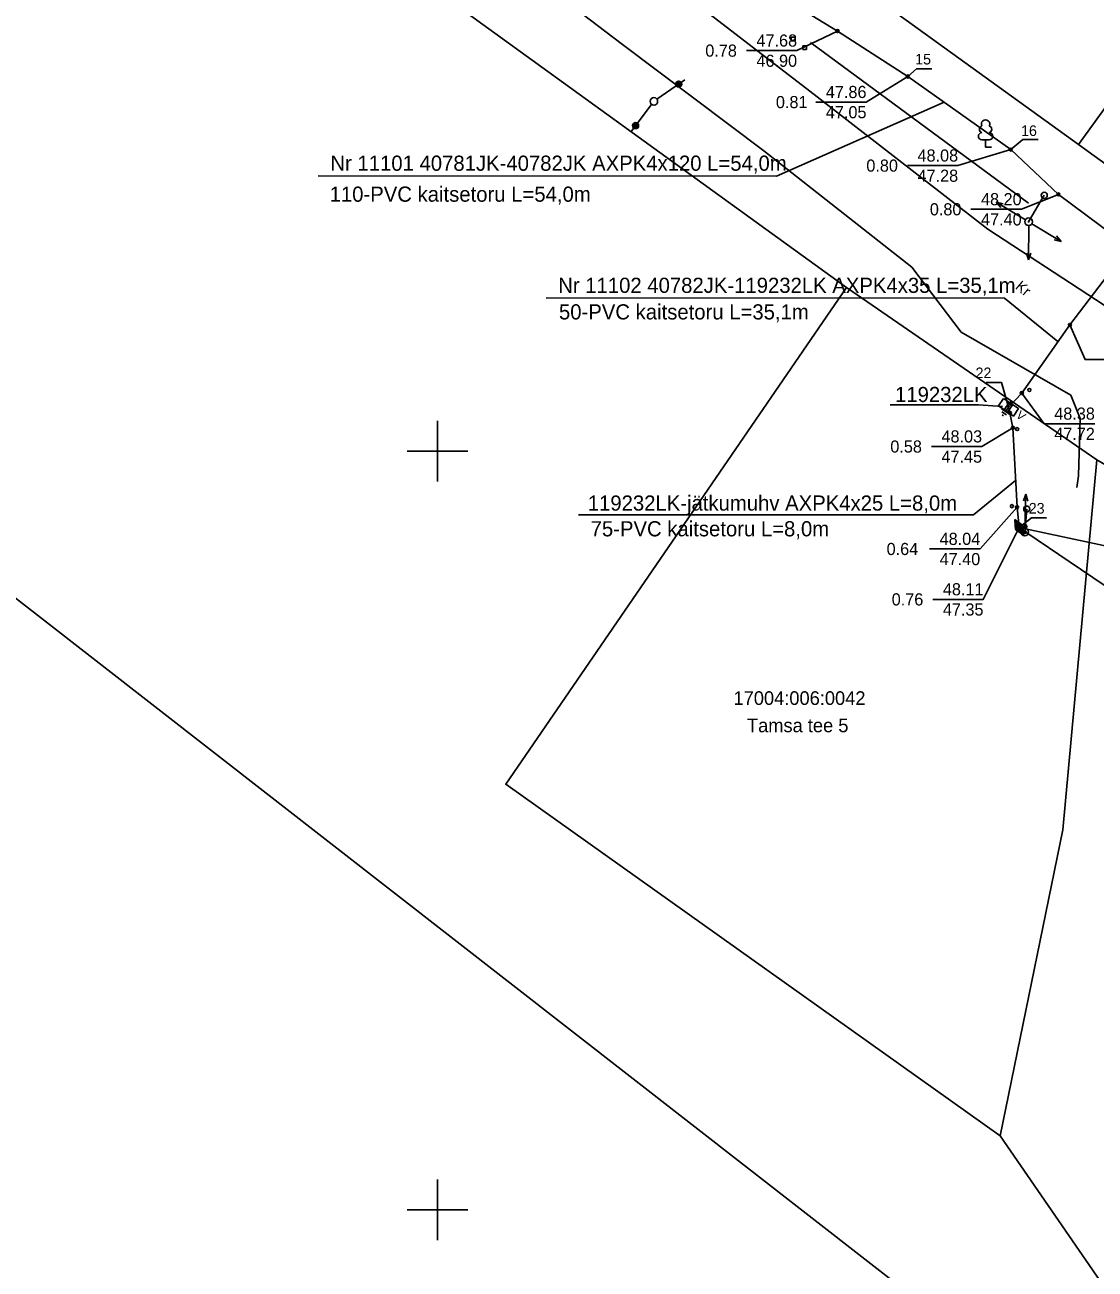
# Model space of a CAD drawing. Extents: x 643977 to 644381, y 6457457 to 6457867.
# Drawn here: x 644122.8 to 644193.3, y 6457546.1 to 6457628.1 of the extents above; entities that cross this region are included whole.
import ezdxf

# ---------------------------------------------------------------- set-up
doc = ezdxf.new("R2010")
doc.units = 0
for name, color, linetype in [('004 MPP EE @ 1 (1)', 7, 'Continuous'), ('005 MPO EE @ 1 (1)', 7, 'Continuous'), ('005 MPO EE @ 1 (2)', 7, 'Continuous'), ('007 PIIR EE', 7, 'Continuous'), ('007 PIIR1 EE', 7, 'Continuous'), ('MOOTMPUNKT', 7, 'Continuous'), ('TEE', 7, 'Continuous'), ('TORU_NR', 7, 'Continuous'), ('UUS', 7, 'Continuous'), ('Veeprojekti jooned$0$0_Hoiatustekst', 7, 'Continuous'), ('VORK', 7, 'Continuous'), ('VORMISTUS', 7, 'Continuous')]:
    doc.layers.add(name, color=color, linetype=linetype)

msp = doc.modelspace()

# ---------------------------------------------------------------- linework, layer by layer
at = {"layer": '004 MPP EE @ 1 (1)'}
for p, q in [((644173.309, 6457627.298), (644173.309, 6457627.048)), ((644173.309, 6457627.298), (644173.559, 6457627.298)), ((644173.559, 6457627.298), (644173.559, 6457627.048)), ((644173.309, 6457627.048), (644173.559, 6457627.048)), ((644174.072, 6457626.717), (644174.072, 6457626.467)), ((644174.072, 6457626.717), (644174.322, 6457626.717)), ((644174.072, 6457626.467), (644174.322, 6457626.467)), ((644174.322, 6457626.717), (644174.322, 6457626.467))]:
    msp.add_line(p, q, dxfattribs=at)
at = {"layer": '005 MPO EE @ 1 (1)'}
for p, q in [((644189.982, 6457616.865), (644188.956, 6457615.125)), ((644187.678, 6457603.219), (644187.342, 6457602.726)), ((644187.902, 6457603.067), (644187.566, 6457602.573)), ((644188.697, 6457594.667), (644188.83, 6457596.183))]:
    msp.add_line(p, q, dxfattribs=at)
msp.add_lwpolyline([(644187.296, 6457603.479), (644188.284, 6457602.807), (644187.948, 6457602.313), (644186.96, 6457602.986)], close=True, dxfattribs=at)
msp.add_lwpolyline([(644179.824, 6457603.066), (644185.644, 6457603.066), (644187.227, 6457602.95)], dxfattribs=at)
for centre, radius in [((644164.252, 6457623.055), 0.25), ((644189.982, 6457616.865), 0.2), ((644188.956, 6457615.125), 0.25), ((644188.956, 6457615.125), 0.0234), ((644188.83, 6457596.183), 0.2), ((644188.697, 6457594.667), 0.25), ((644188.697, 6457594.667), 0.0234)]:
    msp.add_circle(centre, radius, dxfattribs=at)
at = {"layer": '005 MPO EE @ 1 (2)'}
for points in [[(644097.357, 6457696.766), (644100.441, 6457690.483), (644108.831, 6457675.729), (644120.122, 6457661.417), (644132.967, 6457649.318), (644147.713, 6457637.831), (644162.185, 6457626.8)], [(644165.209, 6457630.911), (644174.337, 6457623.878), (644186.272, 6457614.624), (644201.035, 6457604.979), (644215.289, 6457597.386), (644225.394, 6457591.42), (644240.377, 6457581.381), (644253.475, 6457570.785), (644267.864, 6457559.308)], [(644162.185, 6457626.8), (644171.491, 6457619.794), (644181.248, 6457612.122), (644184.497, 6457607.838)], [(644184.497, 6457607.838), (644191.733, 6457603.701), (644192.353, 6457602.158), (644192.243, 6457598.378), (644192.129, 6457597.598)]]:
    msp.add_lwpolyline(points, dxfattribs=at)
at = {"layer": '007 PIIR EE'}
for p, q in [((644186.818, 6457616.421), (644187.126, 6457616.059)), ((644186.818, 6457616.421), (644187.281, 6457616.314)), ((644188.742, 6457615.254), (644186.818, 6457616.421)), ((644188.958, 6457614.861), (644188.954, 6457612.611)), ((644189.169, 6457614.995), (644191.093, 6457613.828)), ((644191.093, 6457613.828), (644190.785, 6457614.191)), ((644191.093, 6457613.828), (644190.63, 6457613.936)), ((644188.954, 6457612.611), (644188.806, 6457613.062)), ((644188.954, 6457612.611), (644189.105, 6457613.061)), ((644188.767, 6457597.166), (644188.605, 6457596.719)), ((644188.704, 6457594.917), (644188.767, 6457597.166)), ((644188.767, 6457597.166), (644188.903, 6457596.71)), ((644188.697, 6457594.667), (644188.697, 6457594.667))]:
    msp.add_line(p, q, dxfattribs=at)
at = {"layer": '007 PIIR1 EE'}
for p, q in [((644188.037, 6457595.497), (644188.561, 6457595.107)), ((644188.037, 6457595.497), (644188.086, 6457594.845)), ((644188.06, 6457595.479), (644188.04, 6457595.45)), ((644188.08, 6457595.464), (644188.043, 6457595.409)), ((644188.1, 6457595.449), (644188.046, 6457595.369)), ((644188.12, 6457595.434), (644188.049, 6457595.328)), ((644188.141, 6457595.42), (644188.052, 6457595.288)), ((644188.161, 6457595.405), (644188.056, 6457595.248)), ((644188.181, 6457595.39), (644188.059, 6457595.207)), ((644188.201, 6457595.375), (644188.062, 6457595.167)), ((644188.221, 6457595.36), (644188.065, 6457595.126)), ((644188.241, 6457595.345), (644188.068, 6457595.086)), ((644188.261, 6457595.33), (644188.071, 6457595.046)), ((644188.281, 6457595.315), (644188.074, 6457595.005)), ((644188.301, 6457595.3), (644188.077, 6457594.965)), ((644188.321, 6457595.285), (644188.08, 6457594.924)), ((644188.341, 6457595.27), (644188.083, 6457594.884)), ((644188.361, 6457595.255), (644188.087, 6457594.845)), ((644188.382, 6457595.24), (644188.107, 6457594.83)), ((644188.402, 6457595.225), (644188.127, 6457594.815)), ((644188.422, 6457595.21), (644188.147, 6457594.8)), ((644188.442, 6457595.195), (644188.167, 6457594.785)), ((644188.462, 6457595.181), (644188.187, 6457594.77)), ((644188.482, 6457595.166), (644188.207, 6457594.755)), ((644188.502, 6457595.151), (644188.227, 6457594.74)), ((644188.522, 6457595.136), (644188.247, 6457594.725)), ((644188.61, 6457594.455), (644188.086, 6457594.845)), ((644188.542, 6457595.121), (644188.267, 6457594.71)), ((644188.561, 6457595.104), (644188.287, 6457594.695)), ((644188.564, 6457595.064), (644188.307, 6457594.68)), ((644188.567, 6457595.023), (644188.328, 6457594.665)), ((644188.57, 6457594.983), (644188.348, 6457594.65)), ((644188.573, 6457594.942), (644188.368, 6457594.635)), ((644188.576, 6457594.902), (644188.388, 6457594.621)), ((644188.579, 6457594.862), (644188.408, 6457594.606)), ((644188.582, 6457594.821), (644188.428, 6457594.591)), ((644188.585, 6457594.781), (644188.448, 6457594.576)), ((644188.588, 6457594.74), (644188.468, 6457594.561)), ((644188.591, 6457594.7), (644188.488, 6457594.546)), ((644188.594, 6457594.66), (644188.508, 6457594.531)), ((644188.597, 6457594.619), (644188.528, 6457594.516)), ((644188.601, 6457594.579), (644188.548, 6457594.501)), ((644188.61, 6457594.455), (644188.561, 6457595.107)), ((644188.604, 6457594.538), (644188.569, 6457594.486)), ((644188.607, 6457594.498), (644188.589, 6457594.471)), ((644188.61, 6457594.457), (644188.609, 6457594.456))]:
    msp.add_line(p, q, dxfattribs=at)
for points in [[(644170.747, 6457632.71), (644170.727, 6457632.25), (644170.665, 6457631.798), (644170.489, 6457631.288), (644176.355, 6457627.696), (644180.988, 6457624.699), (644187.779, 6457619.88), (644190.918, 6457616.922), (644195.569, 6457613.471), (644203.702, 6457608.165), (644207.658, 6457605.551), (644212.132, 6457602.911), (644212.432, 6457603.018), (644212.719, 6457603.524), (644212.727, 6457604.721)], [(644170.747, 6457632.71), (644170.727, 6457632.25), (644170.665, 6457631.798), (644170.489, 6457631.288), (644176.355, 6457627.696), (644180.988, 6457624.699), (644187.779, 6457619.88), (644190.918, 6457616.922), (644195.569, 6457613.471), (644203.702, 6457608.165), (644207.658, 6457605.551), (644212.132, 6457602.911), (644212.432, 6457603.018), (644212.719, 6457603.524), (644212.727, 6457604.721)], [(644176.355, 6457627.696), (644173.682, 6457626.404), (644170.348, 6457626.404)], [(644180.988, 6457624.699), (644178.256, 6457623.012), (644174.922, 6457623.012)], [(644142.134, 6457618.16), (644172.343, 6457618.134), (644183.391, 6457622.999)], [(644187.779, 6457619.88), (644184.297, 6457618.825), (644180.964, 6457618.825)], [(644190.918, 6457616.922), (644188.482, 6457615.945), (644185.148, 6457615.945)], [(644187.622, 6457602.896), (644188.506, 6457603.833), (644191.675, 6457608.319), (644195.483, 6457613.348), (644203.62, 6457608.04), (644207.578, 6457605.424), (644211.895, 6457602.8), (644212.158, 6457602.721), (644212.49, 6457602.886), (644212.75, 6457603.471), (644212.727, 6457604.721)], [(644187.622, 6457602.896), (644188.506, 6457603.833), (644191.675, 6457608.319), (644195.483, 6457613.348), (644203.62, 6457608.04), (644207.578, 6457605.424), (644211.895, 6457602.8), (644212.158, 6457602.721), (644212.49, 6457602.886), (644212.75, 6457603.471), (644212.727, 6457604.721)], [(644157.147, 6457610.11), (644187.357, 6457610.084), (644190.883, 6457607.238)], [(644191.675, 6457608.319), (644192.671, 6457606.04), (644196.005, 6457606.04)], [(644188.506, 6457603.833), (644189.976, 6457601.811), (644193.309, 6457601.811)], [(644187.692, 6457602.437), (644187.168, 6457602.797)], [(644187.496, 6457602.389), (644187.193, 6457602.598)], [(644187.622, 6457602.896), (644187.43, 6457602.617)], [(644187.622, 6457602.896), (644187.715, 6457602.53), (644187.919, 6457601.541), (644188.19, 6457596.306), (644188.326, 6457594.977)], [(644187.622, 6457602.896), (644187.715, 6457602.53), (644187.919, 6457601.541), (644188.19, 6457596.306), (644188.326, 6457594.977)], [(644187.301, 6457602.341), (644187.219, 6457602.398)], [(644187.919, 6457601.541), (644185.877, 6457600.308), (644182.544, 6457600.308)], [(644188.099, 6457598.062), (644185.31, 6457595.795), (644159.293, 6457595.795)], [(644188.19, 6457596.306), (644185.754, 6457593.554), (644182.42, 6457593.554)], [(644188.326, 6457594.977), (644185.968, 6457590.232), (644182.635, 6457590.232)], [(644188.326, 6457594.977), (644188.697, 6457594.667), (644188.76, 6457594.652), (644199.031, 6457587.724)], [(644188.326, 6457594.977), (644194.624, 6457593.629), (644201.578, 6457593.629)]]:
    msp.add_lwpolyline(points, dxfattribs=at)
at = {"layer": 'MOOTMPUNKT'}
for centre in [(644176.355, 6457627.696), (644180.988, 6457624.699), (644187.779, 6457619.88), (644190.918, 6457616.922), (644191.675, 6457608.319), (644188.506, 6457603.833), (644189.002, 6457604.037), (644187.715, 6457602.53), (644187.79, 6457603.143), (644187.919, 6457601.541), (644188.199, 6457601.457), (644187.852, 6457596.376), (644188.19, 6457596.306), (644188.745, 6457595.044), (644188.326, 6457594.977), (644188.697, 6457594.667)]:
    msp.add_circle(centre, 0.1, dxfattribs=at)
at = {"layer": 'TEE'}
msp.add_lwpolyline([(644119.21, 6457655.5), (644137.18, 6457639.57), (644176.94, 6457610.8), (644193.44, 6457599.42), (644220.94, 6457583.42), (644258.83, 6457557.54), (644299.64, 6457526.51), (644330.13, 6457505.12), (644351.66, 6457500.83), (644373.13, 6457501.25), (644368.81, 6457508.24), (644366.6, 6457513.63), (644352.78, 6457513.35), (644335.16, 6457516.88), (644304.29, 6457538.7), (644233.94, 6457592.97), (644213.34, 6457605.08), (644212.32, 6457605.7), (644192.23, 6457620.22), (644172.44, 6457634.51), (644128.57, 6457664.58), (644105.62, 6457695.4)], dxfattribs=at)
for points in [[(644226.91, 6457668.24), (644207.22, 6457681.69), (644202.24, 6457674.99), (644172.44, 6457634.51), (644192.23, 6457620.22), (644221.58, 6457660.75)], [(644239.59, 6457656.82), (644226.91, 6457668.24), (644221.58, 6457660.75), (644192.23, 6457620.22), (644212.32, 6457605.7), (644228.29, 6457625.32), (644245.1, 6457645.66)], [(644176.94, 6457610.8), (644154.49, 6457578.04), (644187.08, 6457554.88), (644191.21, 6457575.04), (644193.44, 6457599.42)], [(644187.08, 6457554.88), (644204.95, 6457528.94), (644258.83, 6457557.54), (644220.94, 6457583.42), (644193.44, 6457599.42), (644191.21, 6457575.04)]]:
    msp.add_lwpolyline(points, close=True, dxfattribs=at)
at = {"layer": 'TORU_NR'}
msp.add_line((644174.581, 6457626.935), (644188.94, 6457616.351), dxfattribs=at)
at = {"layer": 'UUS'}
for points in [[(644180.988, 6457624.699), (644181.573, 6457625.199), (644182.573, 6457625.199)], [(644187.779, 6457619.88), (644188.572, 6457620.543), (644189.572, 6457620.543)], [(644187.622, 6457602.896), (644187.164, 6457604.521), (644186.164, 6457604.521)], [(644188.326, 6457594.977), (644189.137, 6457595.613), (644190.137, 6457595.613)]]:
    msp.add_lwpolyline(points, dxfattribs=at)
at = {"layer": 'Veeprojekti jooned$0$0_Hoiatustekst'}
for p, q in [((644164.457, 6457623.197), (644166.296, 6457624.478)), ((644164.101, 6457622.855), (644162.753, 6457621.065))]:
    msp.add_line(p, q, dxfattribs=at)
for centre, radius in [((644165.889, 6457624.194), 0.199), ((644165.889, 6457624.194), 0.19), ((644165.889, 6457624.194), 0.18), ((644165.889, 6457624.194), 0.171), ((644165.889, 6457624.194), 0.162), ((644165.889, 6457624.194), 0.152), ((644165.889, 6457624.194), 0.143), ((644165.889, 6457624.194), 0.133), ((644165.889, 6457624.194), 0.124), ((644165.889, 6457624.194), 0.114), ((644165.889, 6457624.194), 0.105), ((644165.889, 6457624.194), 0.0953), ((644165.889, 6457624.194), 0.0858), ((644165.889, 6457624.194), 0.0763), ((644165.889, 6457624.194), 0.0669), ((644165.889, 6457624.194), 0.0574), ((644165.889, 6457624.194), 0.0479), ((644165.889, 6457624.194), 0.0385), ((644165.889, 6457624.194), 0.029), ((644165.889, 6457624.194), 0.0195), ((644165.889, 6457624.194), 0.0101), ((644165.889, 6457624.194), 0.00061), ((644163.051, 6457621.461), 0.199), ((644163.051, 6457621.461), 0.19), ((644163.051, 6457621.461), 0.18), ((644163.051, 6457621.461), 0.171), ((644163.051, 6457621.461), 0.162), ((644163.051, 6457621.461), 0.152), ((644163.051, 6457621.461), 0.143), ((644163.051, 6457621.461), 0.133), ((644163.051, 6457621.461), 0.124), ((644163.051, 6457621.461), 0.114), ((644163.051, 6457621.461), 0.105), ((644163.051, 6457621.461), 0.0953), ((644163.051, 6457621.461), 0.0858), ((644163.051, 6457621.461), 0.0763), ((644163.051, 6457621.461), 0.0669), ((644163.051, 6457621.461), 0.0574), ((644163.051, 6457621.461), 0.0479), ((644163.051, 6457621.461), 0.0385), ((644163.051, 6457621.461), 0.029), ((644163.051, 6457621.461), 0.0195), ((644163.051, 6457621.461), 0.0101), ((644163.051, 6457621.461), 0.00061)]:
    msp.add_circle(centre, radius, dxfattribs=at)
at = {"layer": 'VORK'}
for p, q in [((644150, 6457602), (644150, 6457598)), ((644148, 6457600), (644152, 6457600)), ((644150, 6457552), (644150, 6457548)), ((644148, 6457550), (644152, 6457550))]:
    msp.add_line(p, q, dxfattribs=at)
at = {"layer": 'VORMISTUS'}
for p, q in [((644186.356, 6457620.52), (644185.876, 6457620.52)), ((644186.116, 6457620.045), (644186.116, 6457620.52)), ((644186.496, 6457620.045), (644186.116, 6457620.045))]:
    msp.add_line(p, q, dxfattribs=at)
msp.add_lwpolyline([(644374.211, 6457572.346), (644287.823, 6457461.373), (644045.284, 6457650.18), (644131.672, 6457761.153)], close=True, dxfattribs=at)
for centre, radius, start, end in [((644185.946, 6457621.218), 0.233, 109.02174, 253.14154), ((644186.116, 6457621.565), 0.277, 332.5799, 207.4201), ((644186.286, 6457621.218), 0.233, 286.85082, 70.98591), ((644185.878, 6457620.758), 0.238, 90.0016, 269.3953), ((644186.353, 6457620.758), 0.238, 270.6047, 89.9984)]:
    msp.add_arc(centre, radius, start, end, dxfattribs=at)

# ---------------------------------------------------------------- texts
at = {"layer": '005 MPO EE @ 1 (1)'}
msp.add_text('119232LK', height=1, dxfattribs=at).set_placement((644180.149, 6457603.238))
msp.add_text('V', height=0.56, rotation=320.19443, dxfattribs=at).set_placement((644188.077, 6457602.291))
at = {"layer": '005 MPO EE @ 1 (2)'}
msp.add_text('Kr', height=0.7, rotation=320.00064, dxfattribs=at).set_placement((644188.028, 6457610.76))
at = {"layer": '007 PIIR1 EE'}
for s, height, p in [('47.68', 0.8, (644171.015, 6457626.67)), ('0.78', 0.8, (644167.642, 6457626.004)), ('46.90', 0.8, (644171.015, 6457625.337)), ('47.86', 0.8, (644175.589, 6457623.279)), ('0.81', 0.8, (644172.296, 6457622.612)), ('47.05', 0.8, (644175.589, 6457621.946)), ('48.08', 0.8, (644181.63, 6457619.091)), ('Nr 11101 40781JK-40782JK AXPK4x120 L=54,0m', 1, (644142.934, 6457618.483)), ('0.80', 0.8, (644178.257, 6457618.425)), ('47.28', 0.8, (644181.63, 6457617.758)), ('110-PVC kaitsetoru L=54,0m', 1, (644142.881, 6457616.443)), ('48.20', 0.8, (644185.815, 6457616.212)), ('0.80', 0.8, (644182.442, 6457615.545)), ('47.40', 0.8, (644185.815, 6457614.879)), ('Nr 11102 40782JK-119232LK AXPK4x35 L=35,1m', 1, (644157.947, 6457610.434)), ('50-PVC kaitsetoru L=35,1m', 1, (644157.997, 6457608.683)), ('48.38', 0.8, (644190.642, 6457602.077)), ('48.03', 0.8, (644183.21, 6457600.575)), ('47.72', 0.8, (644190.642, 6457600.744)), ('0.58', 0.8, (644179.837, 6457599.908)), ('47.45', 0.8, (644183.21, 6457599.241)), ('119232LK-jätkumuhv AXPK4x25 L=8,0m', 1, (644159.895, 6457596.081)), ('75-PVC kaitsetoru L=8,0m', 1, (644160.085, 6457594.386)), ('48.04', 0.8, (644183.087, 6457593.821)), ('0.64', 0.8, (644179.594, 6457593.154)), ('47.40', 0.8, (644183.087, 6457592.487)), ('48.11', 0.8, (644183.302, 6457590.499)), ('0.76', 0.8, (644179.929, 6457589.832)), ('47.35', 0.8, (644183.302, 6457589.166))]:
    msp.add_text(s, height=height, dxfattribs=at).set_placement(p)
at = {"layer": 'TEE'}
for s, p in [('17004:006:0042', (644169.5, 6457583.274)), ('Tamsa tee 5', (644170.388, 6457581.474))]:
    msp.add_text(s, height=0.9, dxfattribs=at).set_placement(p)
at = {"layer": 'UUS'}
for s, p in [(' 15', (644181.218, 6457625.491)), (' 16', (644188.197, 6457620.776)), (' 22', (644185.197, 6457604.813)), (' 23', (644188.703, 6457595.886))]:
    msp.add_text(s, height=0.7, dxfattribs=at).set_placement(p)

doc.saveas('drawing.dxf')
